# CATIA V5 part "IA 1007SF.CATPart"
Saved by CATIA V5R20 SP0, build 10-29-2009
Part number: IA 1007SF
Revision: ANY
Definition: UNKNOWN
Nomenclature: IA 1007SF
Source: Unknown
Bounding box of the stored display mesh (mm): x -5.35 to 5.35, y -17 to 0, z -5.35 to 5.35
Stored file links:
  C:\Users\Utente\Desktop\IO LAVORO\3D X SITO CF\CUMSA\3D files FA\FA 2007SF\IA 1007SF.CATPart

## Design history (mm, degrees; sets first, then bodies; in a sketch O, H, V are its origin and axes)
Body1 "Cortar-Extruir1" (main body)
  Solid1: solid without history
